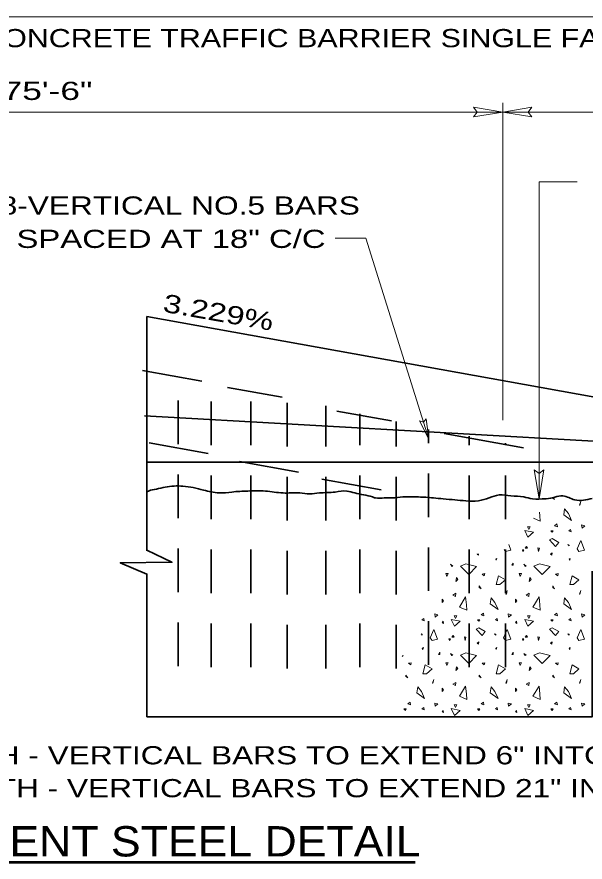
# Model space of a CAD drawing. Extents: x -15.1 to -7.9, y 13.6 to 23.8.
# Drawn here: x -11.694 to -9.819, y 16.811 to 19.599 of the extents above; entities that cross this region are included whole.
import ezdxf
from ezdxf.enums import TextEntityAlignment as Align

# ---------------------------------------------------------------- set-up
doc = ezdxf.new("R2010")
doc.units = 0
doc.header["$LTSCALE"] = 0.024
doc.linetypes.add('LONG_DASHED', pattern=[7.5, 6, -1.5])
for name, color, linetype, lineweight in [('1', 7, 'Continuous', 35), ('10', 7, 'Continuous', 13), ('12', 7, 'Continuous', 53), ('6', 7, 'Continuous', 13)]:
    doc.layers.add(name, color=color, linetype=linetype, lineweight=lineweight)

msp = doc.modelspace()

# ---------------------------------------------------------------- linework, layer by layer
at = {"layer": '1'}
for p, q in [((-11.08417, 18.39733), (-11.27967, 18.4325)), ((-10.81917, 18.3445), (-10.99917, 18.37683)), ((-10.458, 18.2665), (-10.6385, 18.299)), ((-8.59533, 18.13083), (-11.27267, 18.28367)), ((-10.02233, 18.178), (-10.28433, 18.22517)), ((-11.0625, 18.1585), (-11.258, 18.19367)), ((-8.59533, 18.13083), (-11.26617, 18.13083)), ((-10.76433, 18.09717), (-10.95983, 18.13233)), ((-10.49217, 18.039), (-10.68767, 18.07417))]:
    msp.add_line(p, q, dxfattribs=at)
at = {"layer": '1', "linetype": 'LONG_DASHED'}
for p, q in [((-11.16217, 17.45767), (-11.16217, 18.39667)), ((-11.05283, 17.454), (-11.05283, 18.38383)), ((-10.92217, 17.454), (-10.92217, 18.36117)), ((-10.80217, 17.45017), (-10.80217, 18.33867)), ((-10.6745, 17.45017), (-10.6745, 18.316)), ((-10.56217, 17.454), (-10.56217, 18.29017)), ((-10.44217, 17.45017), (-10.44217, 18.26433)), ((-10.33617, 17.46133), (-10.33617, 18.2385)), ((-10.202, 17.454), (-10.202, 18.21583)), ((-10.082, 17.454), (-10.082, 18.19333))]:
    msp.add_line(p, q, dxfattribs=at)
at = {"layer": '1'}
for points in [[(-8.59533, 17.77083), (-8.59533, 18.13083), (-11.26567, 18.61083)], [(-9.7955, 17.77083), (-9.7955, 17.29067), (-11.26567, 17.29067)]]:
    msp.add_lwpolyline(points, dxfattribs=at)
msp.add_spline([(-9.7955, 18.01083), (-9.85317, 18.006), (-9.89217, 18.019), (-9.94717, 18.00933), (-9.9505, 18.00933), (-9.9925, 18.00933), (-10.02167, 18.01567), (-10.06383, 18.019), (-10.10283, 18.02217), (-10.13517, 18.0125), (-10.17083, 18.00283), (-10.213, 18.00283), (-10.2485, 18.006), (-10.2875, 18.00933), (-10.31983, 18.0125), (-10.3685, 18.01567), (-10.42033, 18.01567), (-10.456, 18.0125), (-10.48183, 18.0125), (-10.511, 18.0125), (-10.52083, 18.01567), (-10.57917, 18.02867), (-10.605, 18.03517), (-10.644, 18.03183), (-10.69583, 18.02867), (-10.72817, 18.0255), (-10.7605, 18.02867), (-10.81567, 18.02867), (-10.874, 18.03517), (-10.93233, 18.03517), (-10.98417, 18.03183), (-11.02633, 18.02867), (-11.07817, 18.03833), (-11.14617, 18.05117), (-11.2045, 18.048), (-11.23367, 18.0415), (-11.25967, 18.03517), (-11.26617, 18.03183)], degree=3, dxfattribs=at)
at = {"layer": '10'}
for p, q in [((-13.76867, 19.59917), (-8.606, 19.59917)), ((-10.18683, 19.30117), (-10.09083, 19.28517)), ((-10.18683, 19.30117), (-10.17483, 19.28517)), ((-10.09083, 18.26867), (-10.09083, 19.31567)), ((-9.99483, 19.30117), (-10.09083, 19.28517)), ((-9.99483, 19.30117), (-10.00683, 19.28517)), ((-10.09083, 19.28517), (-13.63867, 19.28517)), ((-10.18683, 19.26917), (-10.09083, 19.28517)), ((-10.18683, 19.26917), (-10.17483, 19.28517)), ((-10.09083, 19.28517), (-8.606, 19.28517)), ((-9.99483, 19.26917), (-10.09083, 19.28517)), ((-9.99483, 19.26917), (-10.00683, 19.28517)), ((-9.84517, 19.05517), (-9.971, 19.05517)), ((-9.971, 19.05517), (-9.971, 18.00933)), ((-10.64333, 18.8695), (-10.5425, 18.8695)), ((-10.5425, 18.8695), (-10.33467, 18.20567)), ((-10.36533, 18.2665), (-10.33467, 18.20567)), ((-10.36533, 18.2665), (-10.35217, 18.26183)), ((-10.344, 18.27317), (-10.35217, 18.26183)), ((-10.344, 18.27317), (-10.33467, 18.20567)), ((-9.987, 18.10533), (-9.971, 18.00933)), ((-9.987, 18.10533), (-9.971, 18.09333)), ((-9.955, 18.10533), (-9.971, 18.00933)), ((-9.955, 18.10533), (-9.971, 18.09333))]:
    msp.add_line(p, q, dxfattribs=at)
at = {"layer": '10', "lineweight": 35}
for p, q in [((-11.26567, 17.8375), (-11.26567, 18.61083)), ((-11.26567, 17.29067), (-11.26567, 17.76217))]:
    msp.add_line(p, q, dxfattribs=at)
msp.add_lwpolyline([(-11.2655, 17.7605), (-11.35267, 17.79867), (-11.18233, 17.8), (-11.2655, 17.8395)], dxfattribs=at)
at = {"layer": '12'}
msp.add_line((-12.67933, 16.811), (-10.37967, 16.811), dxfattribs=at)
at = {"layer": '6'}
for points in [[(-9.92583, 18.012), (-9.92583, 18.01117), (-9.91967, 18.00683), (-9.9235, 18.01233)], [(-9.96967, 17.96567), (-9.96833, 17.9535), (-9.96683, 17.9355), (-9.98917, 17.94517)], [(-10.08633, 17.84233), (-10.08183, 17.8355), (-10.06383, 17.84017), (-10.07083, 17.85867)], [(-10.1745, 17.8275), (-10.17567, 17.8265), (-10.17133, 17.8235), (-10.17033, 17.828)], [(-10.42067, 17.49217), (-10.4195, 17.492), (-10.42217, 17.48933)]]:
    msp.add_lwpolyline(points, dxfattribs=at)
for points in [[(-9.838, 17.9885), (-9.8365, 17.9885), (-9.83367, 18.00067)], [(-9.88667, 17.97617), (-9.8895, 17.95683), (-9.864, 17.93833), (-9.87433, 17.96117)], [(-10.01833, 17.90533), (-10.0075, 17.88267), (-9.9895, 17.89917)], [(-10.009, 17.91717), (-10.00467, 17.90817), (-10, 17.91717)], [(-9.932, 17.90383), (-9.92733, 17.89917), (-9.92433, 17.90383)], [(-9.91217, 17.9265), (-9.91967, 17.92033), (-9.91067, 17.91717)], [(-9.873, 17.90383), (-9.86533, 17.90067), (-9.86683, 17.90817)], [(-9.8305, 17.92333), (-9.829, 17.91283), (-9.82, 17.92033)], [(-9.93667, 17.87367), (-9.91683, 17.85233), (-9.906, 17.86567), (-9.92733, 17.878)], [(-10.01233, 17.85233), (-10.009, 17.84617), (-10.01667, 17.84617)], [(-9.9745, 17.84767), (-9.97267, 17.8355), (-9.96983, 17.84617)], [(-9.8715, 17.85667), (-9.87583, 17.85817), (-9.8715, 17.85383)], [(-9.8395, 17.8355), (-9.8215, 17.84017), (-9.83367, 17.87183), (-9.8455, 17.84483)], [(-10.026, 17.8415), (-10.0245, 17.8355), (-10.02133, 17.8415)], [(-9.93333, 17.8265), (-9.92917, 17.8235), (-9.92733, 17.83117)], [(-10.25883, 17.78567), (-10.256, 17.78717), (-10.26367, 17.79333)], [(-10.21217, 17.79467), (-10.17717, 17.78567), (-10.20317, 17.75983), (-10.2305, 17.78717)], [(-10.1105, 17.81267), (-10.11383, 17.80983), (-10.112, 17.80667)], [(-10.05617, 17.79767), (-10.0605, 17.79), (-10.05617, 17.79)], [(-10.01667, 17.78567), (-10.01367, 17.78717), (-10.02133, 17.79333)], [(-9.96983, 17.79467), (-9.93483, 17.78567), (-9.96083, 17.75983), (-9.98817, 17.78717)], [(-9.86817, 17.81267), (-9.8715, 17.80983), (-9.86967, 17.80667)], [(-10.27867, 17.76267), (-10.27583, 17.75367), (-10.27117, 17.76267)], [(-10.15917, 17.76133), (-10.15167, 17.75517), (-10.15017, 17.76267)], [(-10.03633, 17.76267), (-10.0335, 17.75367), (-10.02883, 17.76267)], [(-9.91683, 17.76133), (-9.90933, 17.75517), (-9.90783, 17.76267)], [(-10.24383, 17.74933), (-10.2455, 17.73717), (-10.2395, 17.74333)], [(-10.10017, 17.72633), (-10.08183, 17.74183), (-10.1045, 17.75517), (-10.112, 17.72633)], [(-10.0015, 17.74933), (-10.00333, 17.73717), (-9.99717, 17.74333)], [(-9.85783, 17.72633), (-9.8395, 17.74183), (-9.86217, 17.75517), (-9.86967, 17.72633)], [(-10.16817, 17.722), (-10.16817, 17.71733), (-10.162, 17.713)], [(-10.08033, 17.69467), (-10.07883, 17.69467), (-10.076, 17.70683)], [(-9.92583, 17.722), (-9.92583, 17.71733), (-9.91967, 17.713)], [(-9.838, 17.69467), (-9.8365, 17.69467), (-9.83367, 17.70683)], [(-10.291, 17.67817), (-10.291, 17.66733), (-10.28633, 17.67333)], [(-10.256, 17.69183), (-10.247, 17.68717), (-10.2455, 17.69783)], [(-10.21067, 17.65967), (-10.20917, 17.64167), (-10.23333, 17.65217), (-10.2135, 17.68567)], [(-10.129, 17.68233), (-10.13183, 17.663), (-10.10617, 17.64467), (-10.11667, 17.66733)], [(-10.04867, 17.67817), (-10.04867, 17.66733), (-10.044, 17.67333)], [(-10.01367, 17.69183), (-10.00467, 17.68717), (-10.00333, 17.69783)], [(-9.96833, 17.65967), (-9.96683, 17.64167), (-9.991, 17.65217), (-9.97117, 17.68567)], [(-9.88667, 17.68233), (-9.8895, 17.663), (-9.864, 17.64467), (-9.87433, 17.66733)], [(-10.315, 17.6295), (-10.31367, 17.619), (-10.30467, 17.62667)], [(-10.25133, 17.62333), (-10.247, 17.61433), (-10.24233, 17.62333)], [(-10.1545, 17.63267), (-10.162, 17.62667), (-10.153, 17.62333)], [(-10.07283, 17.6295), (-10.07133, 17.619), (-10.06233, 17.62667)], [(-10.009, 17.62333), (-10.00467, 17.61433), (-10, 17.62333)], [(-9.91217, 17.63267), (-9.91967, 17.62667), (-9.91067, 17.62333)], [(-9.8305, 17.6295), (-9.829, 17.619), (-9.82, 17.62667)], [(-10.3575, 17.61), (-10.35, 17.60683), (-10.3515, 17.61433)], [(-10.291, 17.60067), (-10.28633, 17.59783), (-10.28767, 17.60533)], [(-10.26067, 17.6115), (-10.24983, 17.58883), (-10.23183, 17.60533)], [(-10.17433, 17.61), (-10.16967, 17.60533), (-10.16667, 17.61)], [(-10.11517, 17.61), (-10.10767, 17.60683), (-10.10917, 17.61433)], [(-10.04867, 17.60067), (-10.044, 17.59783), (-10.04533, 17.60533)], [(-10.01833, 17.6115), (-10.0075, 17.58883), (-9.9895, 17.60533)], [(-9.932, 17.61), (-9.92733, 17.60533), (-9.92433, 17.61)], [(-9.873, 17.61), (-9.86533, 17.60683), (-9.86683, 17.61433)], [(-10.324, 17.54167), (-10.306, 17.54633), (-10.31833, 17.578), (-10.33017, 17.551)], [(-10.179, 17.57983), (-10.15917, 17.5585), (-10.14833, 17.57183), (-10.16967, 17.58417)], [(-10.08183, 17.54167), (-10.06383, 17.54633), (-10.076, 17.578), (-10.08783, 17.551)], [(-9.93667, 17.57983), (-9.91683, 17.5585), (-9.906, 17.57183), (-9.92733, 17.58417)], [(-9.8395, 17.54167), (-9.8215, 17.54633), (-9.83367, 17.578), (-9.8455, 17.551)], [(-10.35617, 17.56283), (-10.3605, 17.56433), (-10.35617, 17.56)], [(-10.26833, 17.54767), (-10.26683, 17.54167), (-10.26367, 17.54767)], [(-10.2545, 17.5585), (-10.25133, 17.5525), (-10.25883, 17.5525)], [(-10.21683, 17.55383), (-10.215, 17.54167), (-10.21217, 17.5525)], [(-10.11383, 17.56283), (-10.11817, 17.56433), (-10.11383, 17.56)], [(-10.026, 17.54767), (-10.0245, 17.54167), (-10.02133, 17.54767)], [(-10.01233, 17.5585), (-10.009, 17.5525), (-10.01667, 17.5525)], [(-9.9745, 17.55383), (-9.97267, 17.54167), (-9.96983, 17.5525)], [(-9.8715, 17.56283), (-9.87583, 17.56433), (-9.8715, 17.56)], [(-10.35283, 17.519), (-10.35617, 17.516), (-10.35433, 17.51283)], [(-10.17567, 17.53267), (-10.17133, 17.52967), (-10.16967, 17.53733)], [(-10.1105, 17.519), (-10.11383, 17.516), (-10.112, 17.51283)], [(-9.93333, 17.53267), (-9.92917, 17.52967), (-9.92733, 17.53733)], [(-9.86817, 17.519), (-9.8715, 17.516), (-9.86967, 17.51283)], [(-10.2985, 17.50383), (-10.30283, 17.49633), (-10.2985, 17.49633)], [(-10.25883, 17.492), (-10.256, 17.49333), (-10.26367, 17.4995)], [(-10.21217, 17.501), (-10.17717, 17.492), (-10.20317, 17.466), (-10.2305, 17.49333)], [(-10.05617, 17.50383), (-10.0605, 17.49633), (-10.05617, 17.49633)], [(-10.01667, 17.492), (-10.01367, 17.49333), (-10.02133, 17.4995)], [(-9.96983, 17.501), (-9.93483, 17.492), (-9.96083, 17.466), (-9.98817, 17.49333)], [(-10.4015, 17.4675), (-10.394, 17.46133), (-10.3925, 17.46883)], [(-10.3425, 17.4325), (-10.324, 17.448), (-10.34683, 17.46133), (-10.35433, 17.4325)], [(-10.27867, 17.46883), (-10.27583, 17.45983), (-10.27117, 17.46883)], [(-10.24383, 17.4555), (-10.2455, 17.44333), (-10.2395, 17.4495)], [(-10.15917, 17.4675), (-10.15167, 17.46133), (-10.15017, 17.46883)], [(-10.10017, 17.4325), (-10.08183, 17.448), (-10.1045, 17.46133), (-10.112, 17.4325)], [(-10.03633, 17.46883), (-10.0335, 17.45983), (-10.02883, 17.46883)], [(-10.0015, 17.4555), (-10.00333, 17.44333), (-9.99717, 17.4495)], [(-9.91683, 17.4675), (-9.90933, 17.46133), (-9.90783, 17.46883)], [(-9.85783, 17.4325), (-9.8395, 17.448), (-9.86217, 17.46133), (-9.86967, 17.4325)], [(-10.4105, 17.42817), (-10.4105, 17.4235), (-10.40433, 17.41917)], [(-10.16817, 17.42817), (-10.16817, 17.4235), (-10.162, 17.41917)], [(-9.92583, 17.42817), (-9.92583, 17.4235), (-9.91967, 17.41917)], [(-10.32267, 17.40083), (-10.32117, 17.40083), (-10.31833, 17.41317)], [(-10.256, 17.398), (-10.247, 17.39333), (-10.2455, 17.404)], [(-10.08033, 17.40083), (-10.07883, 17.40083), (-10.076, 17.41317)], [(-10.01367, 17.398), (-10.00467, 17.39333), (-10.00333, 17.404)], [(-9.838, 17.40083), (-9.8365, 17.40083), (-9.83367, 17.41317)], [(-10.37117, 17.38867), (-10.37417, 17.36917), (-10.3485, 17.35083), (-10.359, 17.3735)], [(-10.291, 17.38433), (-10.291, 17.3735), (-10.28633, 17.37967)], [(-10.21067, 17.36583), (-10.20917, 17.34783), (-10.23333, 17.35833), (-10.2135, 17.39183)], [(-10.129, 17.38867), (-10.13183, 17.36917), (-10.10617, 17.35083), (-10.11667, 17.3735)], [(-10.04867, 17.38433), (-10.04867, 17.3735), (-10.044, 17.37967)], [(-9.96833, 17.36583), (-9.96683, 17.34783), (-9.991, 17.35833), (-9.97117, 17.39183)], [(-9.88667, 17.38867), (-9.8895, 17.36917), (-9.864, 17.35083), (-9.87433, 17.3735)], [(-10.41667, 17.31617), (-10.412, 17.3115), (-10.409, 17.31617)], [(-10.39683, 17.33883), (-10.40433, 17.33283), (-10.39533, 17.3295)], [(-10.3575, 17.31617), (-10.35, 17.313), (-10.3515, 17.3205)], [(-10.315, 17.33567), (-10.31367, 17.32517), (-10.30467, 17.33283)], [(-10.26067, 17.31767), (-10.24983, 17.295), (-10.23183, 17.3115)], [(-10.25133, 17.3295), (-10.247, 17.3205), (-10.24233, 17.3295)], [(-10.17433, 17.31617), (-10.16967, 17.3115), (-10.16667, 17.31617)], [(-10.1545, 17.33883), (-10.162, 17.33283), (-10.153, 17.3295)], [(-10.11517, 17.31617), (-10.10767, 17.313), (-10.10917, 17.3205)], [(-10.07283, 17.33567), (-10.07133, 17.32517), (-10.06233, 17.33283)], [(-10.01833, 17.31767), (-10.0075, 17.295), (-9.9895, 17.3115)], [(-10.009, 17.3295), (-10.00467, 17.3205), (-10, 17.3295)], [(-9.932, 17.31617), (-9.92733, 17.3115), (-9.92433, 17.31617)], [(-9.91217, 17.33883), (-9.91967, 17.33283), (-9.91067, 17.3295)], [(-9.873, 17.31617), (-9.86533, 17.313), (-9.86683, 17.3205)], [(-9.8305, 17.33567), (-9.829, 17.32517), (-9.82, 17.33283)], [(-10.291, 17.30683), (-10.28633, 17.304), (-10.28767, 17.3115)], [(-10.04867, 17.30683), (-10.044, 17.304), (-10.04533, 17.3115)]]:
    msp.add_lwpolyline(points, close=True, dxfattribs=at)

# ---------------------------------------------------------------- texts
at = {"layer": '12'}
for s, height, width, p in [('PAYMENT PER EACH FOR F SHAPE CONCRETE TRAFFIC BARRIER SINGLE FACE END TRANSITION', 0.06001, 1.25, (-11.15954, 19.49917)), ('55\'-6" OR 75\'-6"', 0.06, 1.45, (-11.8605, 19.32517)), ('38-VERTICAL NO.5 BARS', 0.06001, 1.3, (-11.18542, 18.947)), ('SPACED AT 18" C/C', 0.06001, 1.35, (-11.18533, 18.837)), ('REINFORCEMENT STEEL DETAIL', 0.1, 1.1, (-11.53471, 16.82958))]:
    msp.add_text(s, height=height, dxfattribs=dict(at, width=width)).set_placement(p, align=Align.CENTER)
at = {"layer": '12', "width": 1.35}
msp.add_text('3.229%', height=0.06, rotation=350, dxfattribs=at).set_placement((-11.21508, 18.62708))
at = {"layer": '12', "width": 1.3}
for s, p in [('9" FOOTER DEPTH - VERTICAL BARS TO EXTEND 6" INTO FOOTER', (-12.62642, 17.13342)), ('24" FOOTER DEPTH - VERTICAL BARS TO EXTEND 21" INTO FOOTER', (-12.62067, 17.02492))]:
    msp.add_text(s, height=0.06001, dxfattribs=at).set_placement(p)

doc.saveas('drawing.dxf')
